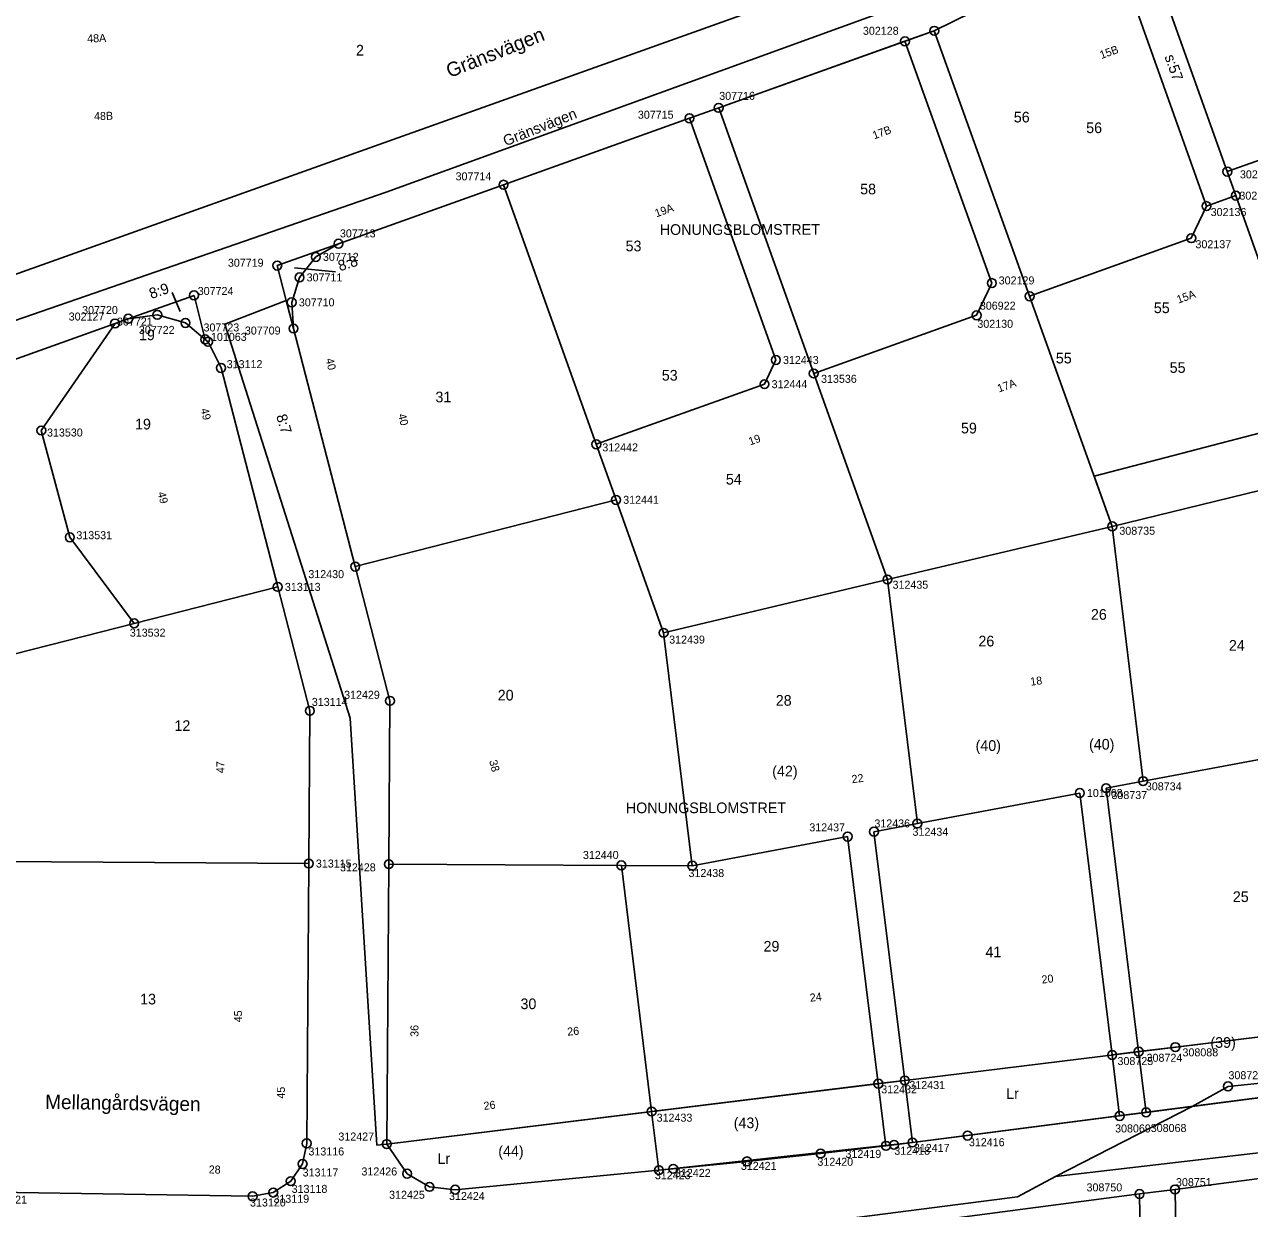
# Model space of a CAD drawing. Extents: x 141995 to 152570, y 6580184 to 6586000.
# Drawn here: x 142748 to 142885.7, y 6585147.6 to 6585280.8 of the extents above; entities that cross this region are included whole.
import ezdxf

# ---------------------------------------------------------------- set-up
doc = ezdxf.new("R2010")
doc.units = 0
for name, color, linetype in [('Level 10', 7, 'Continuous'), ('Level 34', 7, 'Continuous'), ('Level 42', 7, 'Continuous'), ('Level 43', 7, 'Continuous'), ('Level 48', 7, 'Continuous'), ('Level 5', 7, 'Continuous'), ('Level 51', 7, 'Continuous'), ('Level 52', 7, 'Continuous'), ('Level 53', 7, 'Continuous'), ('Level 54', 7, 'Continuous'), ('Level 55', 7, 'Continuous'), ('Level 58', 7, 'Continuous'), ('Level 59', 7, 'Continuous'), ('Level 6', 7, 'Continuous'), ('Level 60', 7, 'Continuous'), ('Level 7', 7, 'Continuous'), ('Level 9', 7, 'Continuous')]:
    doc.layers.add(name, color=color, linetype=linetype)

msp = doc.modelspace()

# ---------------------------------------------------------------- linework, layer by layer
at = {"layer": 'Level 10'}
for centre in [(142850.27, 6585280.1), (142846.98, 6585278.92), (142822.74, 6585270.26), (142826.03, 6585271.43), (142883.23, 6585264.26), (142801.83, 6585262.78), (142884.19, 6585261.56), (142880.89, 6585260.38), (142879.18, 6585256.77), (142783.27, 6585256.15), (142776.38, 6585253.69), (142780.72, 6585254.66), (142778.89, 6585252.36), (142856.75, 6585251.72), (142767.02, 6585250.34), (142778.01, 6585249.55), (142861, 6585250.24), (142762.89, 6585248.15), (142855.04, 6585248.1), (142758.14, 6585247.18), (142759.62, 6585247.71), (142766.06, 6585247.24), (142768.27, 6585245.39), (142778.21, 6585246.61), (142768.6, 6585245.12), (142832.46, 6585243.07), (142770.06, 6585242.18), (142836.72, 6585241.55), (142831.18, 6585240.35), (142749.85, 6585235.14), (142812.26, 6585233.59), (142814.49, 6585227.33), (142870.29, 6585224.35), (142753.05, 6585223.13), (142785.15, 6585219.83), (142845.01, 6585218.38), (142776.44, 6585217.55), (142760.29, 6585213.44), (142819.83, 6585212.38), (142789.06, 6585204.73), (142780.05, 6585203.61), (142869.6, 6585194.91), (142873.76, 6585195.7), (142866.64, 6585194.36), (142848.37, 6585190.93), (142840.53, 6585189.46), (142843.49, 6585190.01), (142779.93, 6585186.43), (142788.93, 6585186.36), (142815.08, 6585186.22), (142823.06, 6585186.18), (142877.39, 6585165.78), (142870.28, 6585164.9), (142873.26, 6585165.27), (142843.98, 6585161.67), (142846.96, 6585162.03), (142883.31, 6585161.36), (142818.48, 6585158.54), (142871.12, 6585158.04), (142874.1, 6585158.44), (142854.02, 6585155.83), (142779.7, 6585154.95), (142788.7, 6585154.87), (142844.84, 6585154.68), (142845.76, 6585154.79), (142847.82, 6585155.05), (142837.49, 6585153.81), (142779.23, 6585152.64), (142819.3, 6585151.94), (142820.92, 6585152.09), (142829.21, 6585152.92), (142777.9, 6585150.7), (142790.99, 6585151.54), (142773.61, 6585149), (142775.93, 6585149.42), (142793.5, 6585150.06), (142796.39, 6585149.74), (142873.36, 6585149.26), (142877.35, 6585149.77)]:
    msp.add_circle(centre, 0.5, dxfattribs=at)
at = {"layer": 'Level 34'}
for points in [[(142868.26, 6585230.02), (142870.29, 6585224.35), (142895.29, 6585230.45), (142916.07, 6585246.27), (142937.08, 6585262.24), (142958.78, 6585278.74), (142987.1, 6585255.56), (142990.76, 6585260.32), (142959.77, 6585285.68), (142924.61, 6585259.72), (142925.59, 6585257.07), (142918.16, 6585254.37), (142918, 6585254.84), (142893.13, 6585236.49)], [(142788.7, 6585154.87), (142790.99, 6585151.54), (142793.5, 6585150.06), (142796.39, 6585149.74), (142819.3, 6585151.94), (142847.82, 6585155.05), (142934.64, 6585166.29), (142936.38, 6585166.79), (142937.9, 6585167.8), (142939.04, 6585169.21), (142939.71, 6585170.9), (142940.31, 6585173.51)]]:
    msp.add_lwpolyline(points, close=True, dxfattribs=at)
at = {"layer": 'Level 5'}
for points in [[(142788.63, 6585261.93), (142867.11, 6585290.45)], [(142845.4, 6585287.91), (142630.63, 6585211.17)], [(142850.27, 6585280.1), (142858.95, 6585284.4)], [(142826.03, 6585271.43), (142846.98, 6585278.92)], [(142846.98, 6585278.92), (142850.27, 6585280.1)], [(142822.74, 6585270.26), (142826.03, 6585271.43)], [(142801.83, 6585262.78), (142822.74, 6585270.26)], [(142783.27, 6585256.15), (142801.83, 6585262.78)], [(142705.99, 6585233.38), (142788.63, 6585261.93)], [(142780.72, 6585254.66), (142783.27, 6585256.15)], [(142778.89, 6585252.36), (142780.72, 6585254.66)], [(142778.01, 6585249.55), (142778.89, 6585252.36)], [(142778.21, 6585246.61), (142778.01, 6585249.55)], [(142758.14, 6585247.18), (142759.62, 6585247.71)], [(142759.62, 6585247.71), (142762.89, 6585248.15)], [(142762.89, 6585248.15), (142766.06, 6585247.24)], [(142766.06, 6585247.24), (142768.27, 6585245.39)], [(142758.14, 6585247.18), (142730.72, 6585237.37)], [(142778.21, 6585246.61), (142785.15, 6585219.83)], [(142768.27, 6585245.39), (142768.6, 6585245.12)], [(142768.6, 6585245.12), (142770.06, 6585242.18)], [(142770.06, 6585242.18), (142776.44, 6585217.55)], [(142789.06, 6585204.73), (142785.15, 6585219.83)], [(142776.44, 6585217.55), (142780.05, 6585203.61)], [(142788.93, 6585186.36), (142789.06, 6585204.73)], [(142780.05, 6585203.61), (142779.93, 6585186.43)], [(142779.93, 6585186.43), (142779.7, 6585154.95)], [(142788.7, 6585154.87), (142788.93, 6585186.36)], [(142896.08, 6585168.08), (142877.39, 6585165.78)], [(142873.26, 6585165.27), (142870.28, 6585164.9)], [(142870.28, 6585164.9), (142871.12, 6585158.04)], [(142877.39, 6585165.78), (142873.26, 6585165.27)], [(142846.96, 6585162.03), (142843.98, 6585161.67)], [(142847.82, 6585155.05), (142846.96, 6585162.03)], [(142843.98, 6585161.67), (142818.48, 6585158.54)], [(142818.48, 6585158.54), (142788.7, 6585154.87)], [(142854.02, 6585155.83), (142871.12, 6585158.04)], [(142779.7, 6585154.95), (142779.23, 6585152.64)], [(142854.02, 6585155.83), (142847.82, 6585155.05)], [(142779.23, 6585152.64), (142777.9, 6585150.7)], [(142877.35, 6585149.77), (142905.22, 6585153.39)], [(142773.61, 6585149), (142744.69, 6585149.45)], [(142775.93, 6585149.42), (142773.61, 6585149)], [(142777.9, 6585150.7), (142775.93, 6585149.42)], [(142873.36, 6585149.26), (142877.35, 6585149.77)], [(142848.55, 6585146.03), (142873.36, 6585149.26)]]:
    msp.add_lwpolyline(points, dxfattribs=at)
at = {"layer": 'Level 51'}
for points in [[(142782.92, 6585253), (142778.33, 6585253.44)], [(142764.55, 6585250.65), (142765.48, 6585248.54)]]:
    msp.add_lwpolyline(points, dxfattribs=at)
at = {"layer": 'Level 6'}
for points in [[(142630.63, 6585211.17), (142845.4, 6585287.91), (142854.33, 6585292.13), (142862.28, 6585298.01), (142868.92, 6585305.33), (142871.58, 6585309.75), (142874.02, 6585313.8), (142876.43, 6585320.51), (142877.36, 6585323.11), (142878.19, 6585328.58), (142878.83, 6585332.88), (142879.02, 6585336.51), (142878.9, 6585336.61), (142862.27, 6585350.99), (142842.95, 6585350.29), (142837.55, 6585350.09), (142808.62, 6585349.03), (142806.35, 6585348.95), (142777.67, 6585347.9), (142772.24, 6585347.7), (142742.4, 6585346.61)], [(142888.7, 6585303.11), (142885.15, 6585304.09), (142881.48, 6585303.72), (142878.19, 6585302.04), (142875.73, 6585299.28), (142872.12, 6585295.41), (142868.31, 6585291.34), (142867.11, 6585290.45), (142858.95, 6585284.4), (142850.27, 6585280.1), (142826.03, 6585271.43), (142822.74, 6585270.26), (142801.83, 6585262.78), (142783.27, 6585256.15), (142780.72, 6585254.66), (142778.89, 6585252.36), (142778.01, 6585249.55), (142778.21, 6585246.61), (142785.15, 6585219.83)], [(142744.69, 6585149.45), (142773.61, 6585149), (142775.93, 6585149.42), (142777.9, 6585150.7), (142779.23, 6585152.64), (142779.7, 6585154.95), (142779.93, 6585186.43), (142780.05, 6585203.61), (142776.44, 6585217.55), (142770.06, 6585242.18), (142768.6, 6585245.12), (142768.27, 6585245.39), (142766.06, 6585247.24), (142762.89, 6585248.15), (142759.62, 6585247.71), (142758.14, 6585247.18), (142730.72, 6585237.37)], [(142785.15, 6585219.83), (142789.06, 6585204.73), (142788.93, 6585186.36), (142788.7, 6585154.87), (142790.99, 6585151.54), (142793.5, 6585150.06), (142796.39, 6585149.74), (142819.3, 6585151.94), (142820.92, 6585152.09), (142829.21, 6585152.92), (142837.49, 6585153.81), (142844.84, 6585154.68), (142845.76, 6585154.79), (142847.82, 6585155.05), (142854.02, 6585155.83), (142871.12, 6585158.04), (142874.1, 6585158.44), (142896.91, 6585161.4)], [(142934.45, 6585124.56), (142936.08, 6585150.19), (142935.67, 6585152.78), (142934.2, 6585154.95), (142931.93, 6585156.29), (142929.32, 6585156.53), (142905.22, 6585153.39), (142877.35, 6585149.77), (142873.36, 6585149.26), (142848.55, 6585146.03)]]:
    msp.add_lwpolyline(points, dxfattribs=at)
at = {"layer": 'Level 7'}
for points in [[(142874.49, 6585288.75), (142883.23, 6585264.26)], [(142871.2, 6585287.57), (142880.89, 6585260.38)], [(142856.75, 6585251.72), (142846.98, 6585278.92)], [(142850.27, 6585280.1), (142861, 6585250.24)], [(142826.03, 6585271.43), (142836.72, 6585241.55)], [(142822.74, 6585270.26), (142832.46, 6585243.07)], [(142883.23, 6585264.26), (142899.25, 6585269.93)], [(142884.19, 6585261.56), (142883.23, 6585264.26)], [(142801.83, 6585262.78), (142812.26, 6585233.59)], [(142880.89, 6585260.38), (142884.19, 6585261.56)], [(142884.19, 6585261.56), (142895.29, 6585230.45)], [(142879.18, 6585256.77), (142880.89, 6585260.38)], [(142776.38, 6585253.69), (142783.27, 6585256.15)], [(142861, 6585250.24), (142879.18, 6585256.77)], [(142777.39, 6585249.78), (142776.38, 6585253.69)], [(142855.04, 6585248.1), (142856.75, 6585251.72)], [(142759.62, 6585247.71), (142767.02, 6585250.34)], [(142767.02, 6585250.34), (142768.27, 6585245.39)], [(142861, 6585250.24), (142870.29, 6585224.35)], [(142777.39, 6585249.78), (142770.48, 6585247.09)], [(142778.21, 6585246.61), (142777.39, 6585249.78)], [(142855.04, 6585248.1), (142836.72, 6585241.55)], [(142758.14, 6585247.18), (142749.85, 6585235.14)], [(142770.48, 6585247.09), (142784.58, 6585202.8)], [(142832.46, 6585243.07), (142831.18, 6585240.35)], [(142831.18, 6585240.35), (142812.26, 6585233.59)], [(142845.01, 6585218.38), (142836.72, 6585241.55)], [(142753.05, 6585223.13), (142749.85, 6585235.14)], [(142812.26, 6585233.59), (142814.49, 6585227.33)], [(142870.29, 6585224.35), (142895.29, 6585230.45)], [(142814.49, 6585227.33), (142785.15, 6585219.83)], [(142814.49, 6585227.33), (142819.83, 6585212.38)], [(142845.01, 6585218.38), (142870.29, 6585224.35)], [(142873.76, 6585195.7), (142870.29, 6585224.35)], [(142760.29, 6585213.44), (142753.05, 6585223.13)], [(142819.83, 6585212.38), (142845.01, 6585218.38)], [(142848.37, 6585190.93), (142845.01, 6585218.38)], [(142760.29, 6585213.44), (142776.44, 6585217.55)], [(142741, 6585208.53), (142760.29, 6585213.44)], [(142823.06, 6585186.18), (142819.83, 6585212.38)], [(142784.58, 6585202.8), (142787.59, 6585154.74)], [(142892.26, 6585199.16), (142873.76, 6585195.7)], [(142869.6, 6585194.91), (142873.76, 6585195.7)], [(142873.26, 6585165.27), (142869.6, 6585194.91)], [(142848.37, 6585190.93), (142866.64, 6585194.36)], [(142866.64, 6585194.36), (142870.28, 6585164.9)], [(142843.49, 6585190.01), (142848.37, 6585190.93)], [(142840.53, 6585189.46), (142823.06, 6585186.18)], [(142843.98, 6585161.67), (142840.53, 6585189.46)], [(142846.96, 6585162.03), (142843.49, 6585190.01)], [(142779.93, 6585186.43), (142745.21, 6585186.67)], [(142788.93, 6585186.36), (142815.08, 6585186.22)], [(142818.48, 6585158.54), (142815.08, 6585186.22)], [(142815.08, 6585186.22), (142823.06, 6585186.18)], [(142896.74, 6585162.74), (142883.31, 6585161.36)], [(142883.31, 6585161.36), (142879.29, 6585159.11)], [(142863.92, 6585151.21), (142879.29, 6585159.11)], [(142863.92, 6585151.21), (142906.68, 6585156.2)], [(142787.59, 6585154.74), (142788.7, 6585154.87)], [(142863.92, 6585151.21), (142859.65, 6585148.93)], [(142877.74, 6585124.4), (142877.35, 6585149.77)], [(142859.65, 6585148.93), (142824.31, 6585144.41)], [(142873.36, 6585149.26), (142874.11, 6585100.59)]]:
    msp.add_lwpolyline(points, dxfattribs=at)
at = {"layer": 'Level 9'}
for points in [[(142874.1, 6585158.44), (142873.26, 6585165.27)], [(142843.98, 6585161.67), (142844.84, 6585154.68)], [(142819.3, 6585151.94), (142818.48, 6585158.54)]]:
    msp.add_lwpolyline(points, dxfattribs=at)

# ---------------------------------------------------------------- texts
at = {"layer": 'Level 42'}
msp.add_text('Gränsvägen', height=1.2, rotation=21.6548, dxfattribs=at).set_placement((142802.07, 6585267.1))
at = {"layer": 'Level 43'}
for s, rotation, p in [('Gränsvägen', 21.6548, (142795.77, 6585274.78)), ('Mellangårdsvägen', 359.1123, (142750.27, 6585158.84))]:
    msp.add_text(s, height=1.6, rotation=rotation, dxfattribs=at).set_placement(p)
at = {"layer": 'Level 48'}
for p in [(142858.37, 6585159.96), (142794.41, 6585152.65)]:
    msp.add_text('Lr', height=1.2, rotation=0.0514, dxfattribs=at).set_placement(p)
at = {"layer": 'Level 51'}
for s, rotation, p in [('2', 0.0493, (142785.24, 6585277.32)), ('s:57', 289.6265, (142876.15, 6585277.2)), ('56', 0.0493, (142867.36, 6585268.59)), ('58', 0.0493, (142841.94, 6585261.7)), ('53', 0.0493, (142815.56, 6585255.3)), ('8:8', 17.4774, (142783.43, 6585253.04)), ('8:9', 19.0164, (142762.22, 6585249.92)), ('55', 0.0493, (142876.75, 6585241.62)), ('31', 0.0514, (142794.17, 6585238.31)), ('19', 0.0514, (142760.39, 6585235.26)), ('8:7', 287.2088, (142776.24, 6585236.77)), ('59', 0.0493, (142853.28, 6585234.81)), ('54', 0.0514, (142826.84, 6585229.06)), ('26', 0.0514, (142855.24, 6585210.85)), ('24', 0.0493, (142883.41, 6585210.37)), ('20', 0.0514, (142801.18, 6585204.77)), ('28', 0.0514, (142832.45, 6585204.18)), ('12', 0.0514, (142764.82, 6585201.34)), ('25', 0.0514, (142883.85, 6585182.1)), ('29', 0.0514, (142831.07, 6585176.52)), ('41', 0.0514, (142856.03, 6585175.88)), ('13', 0.0514, (142760.96, 6585170.58)), ('30', 0.0514, (142803.74, 6585170.05))]:
    msp.add_text(s, height=1.2, rotation=rotation, dxfattribs=at).set_placement(p)
at = {"layer": 'Level 52'}
for s, p in [('(40)', (142867.68, 6585199.24)), ('(42)', (142832.05, 6585196.22)), ('(39)', (142881.33, 6585165.7)), ('(43)', (142827.72, 6585156.66)), ('(44)', (142801.24, 6585153.48))]:
    msp.add_text(s, height=1.2, rotation=0.0514, dxfattribs=at).set_placement(p)
at = {"layer": 'Level 53'}
for s, rotation, p in [('302128', 0.0493, (142842.25, 6585279.65)), ('307716', 0.0493, (142826.09, 6585272.33)), ('307715', 0.0493, (142816.94, 6585270.21)), ('307714', 0.0493, (142796.44, 6585263.28)), ('302189', 0.0493, (142884.65, 6585263.5)), ('302138', 0.0493, (142884.59, 6585261.11)), ('302136', 0.0493, (142881.36, 6585259.26)), ('307713', 0.0514, (142783.43, 6585256.86)), ('302137', 0.0493, (142879.65, 6585255.64)), ('307719', 0.0514, (142770.83, 6585253.56)), ('307712', 0.0514, (142781.52, 6585254.22)), ('307711', 0.0514, (142779.69, 6585251.91)), ('302129', 0.0493, (142857.52, 6585251.57)), ('307724', 0.0514, (142767.44, 6585250.38)), ('307710', 0.0514, (142778.81, 6585249.1)), ('307720', 0.0514, (142754.44, 6585248.24)), ('306922', 0.0493, (142855.4, 6585248.73)), ('302127', 0.0514, (142752.93, 6585247.51)), ('307721', 0.0514, (142758.36, 6585246.94)), ('302130', 0.0493, (142855.12, 6585246.69)), ('307722', 0.0514, (142760.82, 6585246)), ('307723', 0.0514, (142768.09, 6585246.28)), ('101063', 0.0514, (142768.93, 6585245.22)), ('307709', 0.0514, (142772.74, 6585245.93)), ('312443', 0.0493, (142833.26, 6585242.62)), ('313112', 0.0514, (142770.7, 6585242.15)), ('312444', 0.0493, (142831.98, 6585239.9)), ('313536', 0.0493, (142837.54, 6585240.5)), ('313530', 0.0514, (142750.49, 6585234.46)), ('312442', 0.0514, (142812.94, 6585232.79)), ('312441', 0.0514, (142815.29, 6585226.89)), ('313531', 0.0514, (142753.79, 6585222.91)), ('308735', 0.0493, (142871.09, 6585223.41)), ('312430', 0.0514, (142779.88, 6585218.53)), ('313113', 0.0514, (142777.24, 6585217.1)), ('312435', 0.0514, (142845.58, 6585217.34)), ('313532', 0.0514, (142759.8, 6585211.95)), ('312439', 0.0514, (142820.46, 6585211.17)), ('313114', 0.0514, (142780.27, 6585204.16)), ('312429', 0.0514, (142783.9, 6585204.96)), ('308734', 0.0514, (142874.07, 6585194.66)), ('101068', 0.0514, (142867.44, 6585193.91)), ('308737', 0.0514, (142870.2, 6585193.68)), ('312437', 0.0514, (142836.22, 6585190.05)), ('312436', 0.0514, (142843.54, 6585190.49)), ('312434', 0.0514, (142847.83, 6585189.55)), ('313115', 0.0514, (142780.73, 6585185.98)), ('312440', 0.0514, (142810.76, 6585186.94)), ('312428', 0.0514, (142783.44, 6585185.55)), ('312438', 0.0514, (142822.63, 6585184.91)), ('308725', 0.0514, (142870.88, 6585163.76)), ('308724', 0.0514, (142874.15, 6585164.13)), ('308088', 0.0514, (142878.19, 6585164.74)), ('312431', 0.0514, (142847.47, 6585161.06)), ('308729', 0.0514, (142883.36, 6585162.17)), ('312432', 0.0514, (142844.31, 6585160.58)), ('312433', 0.0514, (142819.05, 6585157.39)), ('308069', 0.0514, (142870.61, 6585156.18)), ('308068', 0.0514, (142874.62, 6585156.23)), ('312427', 0.0514, (142783.26, 6585155.27)), ('312416', 0.0514, (142854.17, 6585154.63)), ('313116', 0.0514, (142779.89, 6585153.59)), ('312419', 0.0514, (142840.29, 6585153.32)), ('312418', 0.0514, (142845.78, 6585153.67)), ('312417', 0.0514, (142847.98, 6585153.99)), ('312426', 0.0514, (142785.85, 6585151.34)), ('312421', 0.0514, (142828.52, 6585151.97)), ('312420', 0.0514, (142837.13, 6585152.43)), ('313117', 0.0514, (142779.24, 6585151.23)), ('312423', 0.0514, (142818.85, 6585150.92)), ('312422', 0.0514, (142821.11, 6585151.18)), ('308751', 0.0514, (142877.46, 6585150.14)), ('313118', 0.0514, (142778, 6585149.38)), ('312425', 0.0514, (142788.96, 6585148.72)), ('312424', 0.0514, (142795.7, 6585148.58)), ('308750', 0.0514, (142867.4, 6585149.55)), ('313121', 0.0514, (142744.23, 6585148.17)), ('313120', 0.0514, (142773.32, 6585147.85)), ('313119', 0.0514, (142775.95, 6585148.27))]:
    msp.add_text(s, height=0.9, rotation=rotation, dxfattribs=at).set_placement(p)
at = {"layer": 'Level 54'}
for s, rotation, p in [('48A', 1.8955, (142755.02, 6585278.78)), ('15B', 19.6547, (142869.07, 6585276.92)), ('48B', 1.6517, (142755.79, 6585270.04)), ('17B', 20.1207, (142843.52, 6585267.88)), ('19A', 19.6697, (142819.03, 6585259.11)), ('15A', 19.5547, (142877.73, 6585249.41)), ('17A', 19.5877, (142857.55, 6585239.41)), ('40', 284.5138, (142789.96, 6585236.91)), ('19', 19.6624, (142829.57, 6585233.45)), ('49', 284.5288, (142762.92, 6585228.12)), ('18', 7.5074, (142861.13, 6585206.43)), ('47', 89.5829, (142770.43, 6585196.59)), ('38', 284.5318, (142800.21, 6585197.96)), ('22', 7.2444, (142841.04, 6585195.46)), ('20', 7.0574, (142862.4, 6585172.92)), ('24', 6.7164, (142836.33, 6585170.88)), ('45', 89.5949, (142772.41, 6585168.57)), ('26', 5.4874, (142809.04, 6585167.06))]:
    msp.add_text(s, height=0.9, rotation=rotation, dxfattribs=at).set_placement(p)
at = {"layer": 'Level 55'}
for s, rotation, p in [('40', 283.6948, (142781.82, 6585243.16)), ('49', 284.5288, (142767.75, 6585237.53)), ('36', 89.6959, (142792.26, 6585166.93)), ('45', 89.5949, (142777.24, 6585159.98)), ('26', 7.0204, (142799.65, 6585158.71)), ('28', 359.1003, (142768.67, 6585151.57))]:
    msp.add_text(s, height=0.9, rotation=rotation, dxfattribs=at).set_placement(p)
at = {"layer": 'Level 58'}
for rotation, p in [(0.0493, (142819.4, 6585257.14)), (0.0514, (142815.59, 6585192.09))]:
    msp.add_text('HONUNGSBLOMSTRET', height=1.2, rotation=rotation, dxfattribs=at).set_placement(p)
at = {"layer": 'Level 59'}
for s, rotation, p in [('56', 0.0493, (142859.22, 6585269.79)), ('55', 0.0493, (142874.97, 6585248.34)), ('19', 0.0514, (142760.83, 6585245.29)), ('19', 0.0514, (142760.83, 6585245.29)), ('55', 0.0493, (142863.95, 6585242.68)), ('53', 0.0514, (142819.63, 6585240.75)), ('26', 0.0493, (142867.89, 6585213.85))]:
    msp.add_text(s, height=1.2, rotation=rotation, dxfattribs=at).set_placement(p)
at = {"layer": 'Level 60'}
msp.add_text('(40)', height=1.2, rotation=0.0514, dxfattribs=at).set_placement((142854.92, 6585199.1))

doc.saveas('drawing.dxf')
